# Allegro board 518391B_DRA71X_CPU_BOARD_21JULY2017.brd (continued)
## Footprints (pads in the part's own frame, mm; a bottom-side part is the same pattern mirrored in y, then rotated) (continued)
JMP402-25
  rect 0.635x0.635 smd: 1(-0.508,0)
  round 0.635 smd: 2(0.508,0) 3(1.524,0)
JUMP1X2-5635-2MM
  rect 1.422x1.422 hole 0.889: 1(0,0)
  round 1.422 hole 0.889: 2(1.981,0)
JUMP1X2-6040
  rect 1.524x1.524 hole 1.016: 1(0,0)
  round 1.524 hole 1.016: 2(0,-2.54)
JUMP1X5-6040
  rect 1.524x1.524 hole 1.016: 1(0,0)
  round 1.524 hole 1.016: 2(0,-2.54) 3(0,-5.08) 4(0,-7.62) 5(0,-10.16)
JUMP2X6-5432-2MM
  rect 1.372x1.372 hole 0.813: 1(0,0)
  round 1.372 hole 0.813: 2(1.981,0) 3(0,-1.981) 4(1.981,-1.981) 5(0,-3.962) 6(1.981,-3.962) 7(0,-5.944) 8(1.981,-5.944) 9(0,-7.925) 10(1.981,-7.925) 11(0,-9.906) 12(1.981,-9.906)
JUMP2X7-6040
  rect 1.524x1.524 hole 1.016: 1(0,0)
  round 1.524 hole 1.016: 2(2.54,0) 3(0,-2.54) 4(2.54,-2.54) 5(0,-5.08) 6(2.54,-5.08) 7(0,-7.62) 8(2.54,-7.62) 9(0,-10.16) 10(2.54,-10.16) 11(0,-12.7) 12(2.54,-12.7) 13(0,-15.24) 14(2.54,-15.24)
L402-25
  round 0.635 smd: 1(-0.508,0) 2(0.508,0)
L603-35X45
  oval 0.889x1.143 smd: 1(-0.762,0) 2(0.762,0)
L805-35X60
  oval 0.889x1.524 smd: 1(-0.965,0) 2(0.965,0)
LED603-35X45-REV
  oval 0.889x1.143 smd: 1(0.762,0) 2(-0.762,0)
LED1206-59X59
  rect 1.499x1.499 smd: 1(-1.753,0) 2(1.753,0)
MHP93-200
  round 5.08 hole 2.362: 1(0,0)
MHP125-250
  round 6.35 hole 3.175: 1(0,0)
MOLEX-34826-0124
  round 1.524 hole 0.991: 1(-7.01,1.295) 2(-5.004,1.295) 3(5.004,1.295) 4(7.01,1.295) 5(-7.01,-0.914) 6(-5.004,-0.914) 7(-2.997,-0.914) 8(-0.991,-0.914) 9(0.991,-0.914) 10(2.997,-0.914) 11(5.004,-0.914) 12(7.01,-0.914)
  round 3.556 hole 2.54: 13(-9.855,0) 14(9.855,0)
MOLEX-49225-201
  rect 0.787x1.778 smd: 1(-3.876,10.744) 2(-2.776,10.744) 3(-1.676,10.744) 4(-0.577,10.744) 5(0.523,10.744) 6(1.623,10.744) 7(2.723,10.744) 8(3.823,10.744)
  rect 1.524x2.794 smd: 9(5.893,8.153)
  rect 1.524x2.159 smd: 10(5.893,0.47)
  rect 1.753x2.21 smd: 11(5.893,-4.128) 12(-8.712,-5.144)
  rect 1.702x3.81 smd: 13(-9.398,-0.483)
  rect 1.397x3.556 smd: 14(-9.398,9.03)
  rect 1.6x1.524 smd: 15(-5.969,10.744)
NEO-M8U
  rect 0.787x1.524 smd: 1(-7,-5.88) 2(-5.9,-5.88) 3(-4.801,-5.88) 4(-3.701,-5.88) 5(-2.601,-5.88) 6(-1.501,-5.88) 7(-0.401,-5.88) 8(2.598,-5.88) 9(3.698,-5.88) 10(4.798,-5.88) 11(5.898,-5.88) 12(6.998,-5.88) 13(6.998,5.88) 14(5.898,5.88) 15(4.798,5.88) 16(3.698,5.88) 17(2.598,5.88) 18(-0.401,5.88) 19(-1.501,5.88) 20(-2.601,5.88) 21(-3.701,5.88) 22(-4.801,5.88) 23(-5.9,5.88) 24(-7,5.88)
OSC-KC2520
  rect 1.041x0.94 smd: 1(-0.914,-0.724) 2(0.914,-0.724) 3(0.914,0.724) 4(-0.914,0.724)
PM64-12X70
  oval 0.305x1.778 smd: 1(-3.749,-5.74) 2(-3.249,-5.74) 3(-2.749,-5.74) 4(-2.249,-5.74) 5(-1.75,-5.74) 6(-1.25,-5.74) 7(-0.75,-5.74) 8(-0.25,-5.74) 9(0.25,-5.74) 10(0.75,-5.74) 11(1.25,-5.74) 12(1.75,-5.74) 13(2.249,-5.74) 14(2.749,-5.74) 15(3.249,-5.74) 16(3.749,-5.74) 33(3.749,5.74) 34(3.249,5.74) 35(2.749,5.74) 36(2.249,5.74) 37(1.75,5.74) 38(1.25,5.74) 39(0.75,5.74) 40(0.25,5.74) 41(-0.25,5.74) 42(-0.75,5.74) 43(-1.25,5.74) 44(-1.75,5.74) 45(-2.249,5.74) 46(-2.749,5.74) 47(-3.249,5.74) 48(-3.749,5.74)
  oval 1.778x0.305 smd: 17(5.74,-3.749) 18(5.74,-3.249) 19(5.74,-2.749) 20(5.74,-2.249) 21(5.74,-1.75) 22(5.74,-1.25) 23(5.74,-0.75) 24(5.74,-0.25) 25(5.74,0.25) 26(5.74,0.75) 27(5.74,1.25) 28(5.74,1.75) 29(5.74,2.249) 30(5.74,2.749) 31(5.74,3.249) 32(5.74,3.749) 49(-5.74,3.749) 50(-5.74,3.249) 51(-5.74,2.749) 52(-5.74,2.249) 53(-5.74,1.75) 54(-5.74,1.25) 55(-5.74,0.75) 56(-5.74,0.25) 57(-5.74,-0.25) 58(-5.74,-0.75) 59(-5.74,-1.25) 60(-5.74,-1.75) 61(-5.74,-2.249) 62(-5.74,-2.749) 63(-5.74,-3.249) 64(-5.74,-3.749)
POWERMITE-CASE457-04
  rect 2.667x2.54 smd: 1(0,0)
  rect 0.762x1.27 smd: 2(2.349,0)
PW14-12X70
  oval 0.305x1.778 smd: 1(-1.951,-3.048) 2(-1.3,-3.048) 3(-0.65,-3.048) 4(0,-3.048) 5(0.65,-3.048) 6(1.3,-3.048) 7(1.951,-3.048) 8(1.951,3.048) 9(1.3,3.048) 10(0.65,3.048) 11(0,3.048) 12(-0.65,3.048) 13(-1.3,3.048) 14(-1.951,3.048)
PWP14-14X70-PAD
  oval 0.356x1.778 smd: 1(-1.951,-2.987) 2(-1.3,-2.987) 3(-0.65,-2.987) 4(0,-2.987) 5(0.65,-2.987) 6(1.3,-2.987) 7(1.951,-2.987) 8(1.951,2.987) 9(1.3,2.987) 10(0.65,2.987) 11(0,2.987) 12(-0.65,2.987) 13(-1.3,2.987) 14(-1.951,2.987)
  rect 3.302x2.794 smd: 15(0,0)
PWP16-14X70-PAD
  oval 0.356x1.778 smd: 1(-2.276,-2.987) 2(-1.626,-2.987) 3(-0.975,-2.987) 4(-0.325,-2.987) 5(0.325,-2.987) 6(0.975,-2.987) 7(1.626,-2.987) 8(2.276,-2.987) 9(2.276,2.987) 10(1.626,2.987) 11(0.975,2.987) 12(0.325,2.987) 13(-0.325,2.987) 14(-0.975,2.987) 15(-1.626,2.987) 16(-2.276,2.987)
  rect 4.572x3.048 smd: 17(0,0)
PWP28-14X70
  oval 0.356x1.778 smd: 1(-4.227,-2.921) 2(-3.576,-2.921) 3(-2.926,-2.921) 4(-2.276,-2.921) 5(-1.626,-2.921) 6(-0.975,-2.921) 7(-0.325,-2.921) 8(0.325,-2.921) 9(0.975,-2.921) 10(1.626,-2.921) 11(2.276,-2.921) 12(2.926,-2.921) 13(3.576,-2.921) 14(4.227,-2.921) 15(4.227,2.921) 16(3.576,2.921) 17(2.926,2.921) 18(2.276,2.921) 19(1.626,2.921) 20(0.975,2.921) 21(0.325,2.921) 22(-0.325,2.921) 23(-0.975,2.921) 24(-1.626,2.921) 25(-2.276,2.921) 26(-2.926,2.921) 27(-3.576,2.921) 28(-4.227,2.921)
  rect 7.62x2.54 smd: 29(0,0)
PWR-Q5A-SLPS319
  rect 0.711x1.397 smd: 1(-1.905,0) 2(-0.635,0) 3(0.635,0) 4(1.905,0)
  custom 1.111x1.111 smd: 5(0,2.781)
PWRJACK-CUI-PJ063BH
  round 1.092 hole 1.6 unplated: (0,-3)
  oval 3.81x1.778 hole 2.997x1.016: 1(0,-12)
  oval 3.073x1.778 hole 2.311x1.016: 2(0,-6)
  oval 1.778x3.302 hole 1.016x2.489: MTG1(-4.5,-5) MTG2(4.5,-5)
QFN32_5X5
  oval 0.254x0.838 smd: 1(-1.751,-2.515) 8(1.751,-2.515) 17(1.751,2.515) 24(-1.751,2.515)
  rect 0.254x0.838 smd: 2(-1.251,-2.515) 3(-0.751,-2.515) 4(-0.25,-2.515) 5(0.25,-2.515) 6(0.751,-2.515) 7(1.251,-2.515) 18(1.251,2.515) 19(0.751,2.515) 20(0.25,2.515) 21(-0.25,2.515) 22(-0.751,2.515) 23(-1.251,2.515)
  oval 0.838x0.254 smd: 9(2.515,-1.751) 16(2.515,1.751) 25(-2.515,1.751) 32(-2.515,-1.751)
  rect 0.838x0.254 smd: 10(2.515,-1.251) 11(2.515,-0.751) 12(2.515,-0.25) 13(2.515,0.25) 14(2.515,0.751) 15(2.515,1.251) 26(-2.515,1.251) 27(-2.515,0.751) 28(-2.515,0.25) 29(-2.515,-0.25) 30(-2.515,-0.751) 31(-2.515,-1.251)
  rect 3.404x3.404 smd: 33(0,0)
QFN84-12X12
  oval 0.889x0.279 smd: 1(-5.944,5.001) 2(-5.944,4.501) 3(-5.944,4) 4(-5.944,3.5) 5(-5.944,3) 6(-5.944,2.499) 7(-5.944,2.002) 8(-5.944,1.501) 9(-5.944,1.001) 10(-5.944,0.5) 11(-5.944,0) 12(-5.944,-0.5) 13(-5.944,-1.001) 14(-5.944,-1.501) 15(-5.944,-2.002) 16(-5.944,-2.499) 17(-5.944,-3) 18(-5.944,-3.5) 19(-5.944,-4) 20(-5.944,-4.501) 21(-5.944,-5.001) 43(5.944,-5.001) 44(5.944,-4.501) 45(5.944,-4) 46(5.944,-3.5) 47(5.944,-3.002) 48(5.944,-2.502) 49(5.944,-2.002) 50(5.944,-1.501) 51(5.944,-1.001) 52(5.944,-0.5) 53(5.944,0) 54(5.944,0.5) 55(5.944,1.001) 56(5.944,1.501) 57(5.944,2.002) 58(5.944,2.499) 59(5.944,3) 60(5.944,3.5) 61(5.944,4) 62(5.944,4.501) 63(5.944,5.001)
  oval 0.279x0.889 smd: 22(-5.001,-5.944) 23(-4.501,-5.944) 24(-4,-5.944) 25(-3.5,-5.944) 26(-3,-5.944) 27(-2.499,-5.944) 28(-2.002,-5.944) 29(-1.501,-5.944) 30(-1.001,-5.944) 31(-0.5,-5.944) 32(0,-5.944) 33(0.5,-5.944) 34(1.001,-5.944) 35(1.501,-5.944) 36(2.002,-5.944) 37(2.499,-5.944) 38(3,-5.944) 39(3.5,-5.944) 40(4,-5.944) 41(4.501,-5.944) 42(5.001,-5.944) 64(5.001,5.944) 65(4.501,5.944) 66(4,5.944) 67(3.5,5.944) 68(3.002,5.944) 69(2.502,5.944) 70(2.002,5.944) 71(1.501,5.944) 72(1.001,5.944) 73(0.5,5.944) 74(0,5.944) 75(-0.5,5.944) 76(-1.001,5.944) 77(-1.501,5.944) 78(-2.002,5.944) 79(-2.499,5.944) 80(-3,5.944) 81(-3.5,5.944) 82(-4,5.944) 83(-4.501,5.944) 84(-5.001,5.944)
  rect 5.588x5.588 smd: 85(0,0)
QSH-020-DP-A
  round 0.508 hole 1.016 unplated: (-10.06,2.667) (10.06,2.667)
  rect 0.279x2.273 smd: 1(-7.248,-2.864) 2(-7.248,2.864) 3(-6.748,-2.864) 4(-6.748,2.864) 5(-5.749,-2.864) 6(-5.749,2.864) 7(-5.249,-2.864) 8(-5.249,2.864) 9(-4.249,-2.864) 10(-4.249,2.864) 11(-3.749,-2.864) 12(-3.749,2.864) 13(-2.749,-2.864) 14(-2.749,2.864) 15(-2.249,-2.864) 16(-2.249,2.864) 17(-1.25,-2.864) 18(-1.25,2.864) 19(-0.75,-2.864) 20(-0.75,2.864) 21(0.25,-2.864) 22(0.25,2.864) 23(0.75,-2.864) 24(0.75,2.864) 25(1.75,-2.864) 26(1.75,2.864) 27(2.249,-2.864) 28(2.249,2.864) 29(3.249,-2.864) 30(3.249,2.864) 31(3.749,-2.864) 32(3.749,2.864) 33(4.749,-2.864) 34(4.749,2.864) 35(5.249,-2.864) 36(5.249,2.864) 37(6.248,-2.864) 38(6.248,2.864) 39(6.748,-2.864) 40(6.748,2.864)
  rect 2.54x0.432 smd: 41(-8.065,0) 44(8.065,0)
  rect 4.699x0.432 smd: 42(-3.175,0) 43(3.175,0)
QSH-030-01-F
  round 0.508 hole 1.016 unplated: (-10.061,2.667) (10.061,2.667)
  rect 0.279x2.273 smd: 1(-7.249,-2.865) 2(-7.249,2.865) 3(-6.749,-2.865) 4(-6.749,2.865) 5(-6.248,-2.865) 6(-6.248,2.865) 7(-5.748,-2.865) 8(-5.748,2.865) 9(-5.248,-2.865) 10(-5.248,2.865) 11(-4.75,-2.865) 12(-4.75,2.865) 13(-4.249,-2.865) 14(-4.249,2.865) 15(-3.749,-2.865) 16(-3.749,2.865) 17(-3.249,-2.865) 18(-3.249,2.865) 19(-2.748,-2.865) 20(-2.748,2.865) 21(-2.25,-2.865) 22(-2.25,2.865) 23(-1.75,-2.865) 24(-1.75,2.865) 25(-1.25,-2.865) 26(-1.25,2.865) 27(-0.749,-2.865) 28(-0.749,2.865) 29(-0.249,-2.865) 30(-0.249,2.865) 31(0.249,-2.865) 32(0.249,2.865) 33(0.749,-2.865) 34(0.749,2.865) 35(1.25,-2.865) 36(1.25,2.865) 37(1.75,-2.865) 38(1.75,2.865) 39(2.25,-2.865) 40(2.25,2.865) 41(2.748,-2.865) 42(2.748,2.865) 43(3.249,-2.865) 44(3.249,2.865) 45(3.749,-2.865) 46(3.749,2.865) 47(4.249,-2.865) 48(4.249,2.865) 49(4.75,-2.865) 50(4.75,2.865) 51(5.248,-2.865) 52(5.248,2.865) 53(5.748,-2.865) 54(5.748,2.865) 55(6.248,-2.865) 56(6.248,2.865) 57(6.749,-2.865) 58(6.749,2.865) 59(7.249,-2.865) 60(7.249,2.865)
  rect 2.54x0.432 smd: 61(-8.065,0) 64(8.065,0)
  rect 4.699x0.432 smd: 62(-3.175,0) 63(3.175,0)
R201-6P6SPC
  rect 0.47x0.381 smd: 1(-0.343,0) 2(0.343,0)
R402-25
  round 0.635 smd: 1(-0.508,0) 2(0.508,0)
R603-35X45
  oval 0.889x1.143 smd: 1(-0.762,0) 2(0.762,0)
R0612
  rect 3.175x0.889 smd: 1(0,-0.813) 2(0,0.813)
R1206-40X70
  oval 1.016x1.778 smd: 1(-1.524,0) 2(1.524,0)
RGE24-11X28-4MM
  rect 0.711x0.279 smd: 1(-1.905,1.245) 2(-1.905,0.747) 3(-1.905,0.249) 4(-1.905,-0.249) 5(-1.905,-0.747) 6(-1.905,-1.245) 13(1.905,-1.245) 14(1.905,-0.747) 15(1.905,-0.249) 16(1.905,0.249) 17(1.905,0.747) 18(1.905,1.245)
  rect 0.279x0.711 smd: 7(-1.245,-1.905) 8(-0.747,-1.905) 9(-0.249,-1.905) 10(0.249,-1.905) 11(0.747,-1.905) 12(1.245,-1.905) 19(1.245,1.905) 20(0.747,1.905) 21(0.249,1.905) 22(-0.249,1.905) 23(-0.747,1.905) 24(-1.245,1.905)
  rect 2.464x2.464 smd: 25(0,0)
RGY16-12X34
  oval 0.864x0.305 smd: 1(-2.032,-0.749) 8(2.032,-0.749) 9(2.032,0.749) 16(-2.032,0.749)
  oval 0.305x0.864 smd: 2(-1.252,-1.765) 3(-0.752,-1.765) 4(-0.251,-1.765) 5(0.249,-1.765) 6(0.749,-1.765) 7(1.25,-1.765) 10(1.25,1.765) 11(0.749,1.765) 12(0.249,1.765) 13(-0.251,1.765) 14(-0.752,1.765) 15(-1.252,1.765)
  rect 2.489x2.032 smd: 17(0,0)
RGZ48-11X34
  rect 0.279x0.864 smd: 1(-2.748,-3.531) 2(-2.25,-3.531) 3(-1.75,-3.531) 4(-1.25,-3.531) 5(-0.749,-3.531) 6(-0.249,-3.531) 7(0.249,-3.531) 8(0.749,-3.531) 9(1.25,-3.531) 10(1.75,-3.531) 11(2.25,-3.531) 12(2.748,-3.531) 25(2.748,3.531) 26(2.25,3.531) 27(1.75,3.531) 28(1.25,3.531) 29(0.749,3.531) 30(0.249,3.531) 31(-0.249,3.531) 32(-0.749,3.531) 33(-1.25,3.531) 34(-1.75,3.531) 35(-2.25,3.531) 36(-2.748,3.531)
  rect 0.864x0.279 smd: 13(3.531,-2.748) 14(3.531,-2.25) 15(3.531,-1.75) 16(3.531,-1.25) 17(3.531,-0.749) 18(3.531,-0.249) 19(3.531,0.249) 20(3.531,0.749) 21(3.531,1.25) 22(3.531,1.75) 23(3.531,2.25) 24(3.531,2.748) 37(-3.531,2.748) 38(-3.531,2.25) 39(-3.531,1.75) 40(-3.531,1.25) 41(-3.531,0.749) 42(-3.531,0.249) 43(-3.531,-0.249) 44(-3.531,-0.749) 45(-3.531,-1.25) 46(-3.531,-1.75) 47(-3.531,-2.25) 48(-3.531,-2.748)
  rect 5.334x5.334 smd: 49(0,0)
RHS48-11X34
  rect 0.279x0.864 smd: 1(-2.748,-3.531) 2(-2.25,-3.531) 3(-1.75,-3.531) 4(-1.25,-3.531) 5(-0.749,-3.531) 6(-0.249,-3.531) 7(0.249,-3.531) 8(0.749,-3.531) 9(1.25,-3.531) 10(1.75,-3.531) 11(2.25,-3.531) 12(2.748,-3.531) 25(2.748,3.531) 26(2.25,3.531) 27(1.75,3.531) 28(1.25,3.531) 29(0.749,3.531) 30(0.249,3.531) 31(-0.249,3.531) 32(-0.749,3.531) 33(-1.25,3.531) 34(-1.75,3.531) 35(-2.25,3.531) 36(-2.748,3.531)
  rect 0.864x0.279 smd: 13(3.531,-2.748) 14(3.531,-2.25) 15(3.531,-1.75) 16(3.531,-1.25) 17(3.531,-0.749) 18(3.531,-0.249) 19(3.531,0.249) 20(3.531,0.749) 21(3.531,1.25) 22(3.531,1.75) 23(3.531,2.25) 24(3.531,2.748) 37(-3.531,2.748) 38(-3.531,2.25) 39(-3.531,1.75) 40(-3.531,1.25) 41(-3.531,0.749) 42(-3.531,0.249) 43(-3.531,-0.249) 44(-3.531,-0.749) 45(-3.531,-1.25) 46(-3.531,-1.75) 47(-3.531,-2.25) 48(-3.531,-2.748)
  rect 5.334x5.334 smd: 49(0,0)
RKT24
  rect 0.203x0.965 smd: 1(-1.806,-0.965) 2(-1.405,-0.965) 3(-1.003,-0.965) 4(-0.602,-0.965) 5(-0.201,-0.965) 6(0.201,-0.965) 7(0.602,-0.965) 8(1.003,-0.965) 9(1.405,-0.965) 10(1.806,-0.965) 13(1.806,0.965) 14(1.405,0.965) 15(1.003,0.965) 16(0.602,0.965) 17(0.201,0.965) 18(-0.201,0.965) 19(-0.602,0.965) 20(-1.003,0.965) 21(-1.405,0.965) 22(-1.806,0.965)
  rect 0.965x0.203 smd: 11(1.981,-0.201) 12(1.981,0.201) 23(-1.981,0.201) 24(-1.981,-0.201)
RND36-24X10
  oval 0.254x0.61 smd: 1(-2.002,-2.896) 2(-1.501,-2.896) 3(-1.001,-2.896) 4(-0.5,-2.896) 5(0,-2.896) 6(0.498,-2.896) 7(0.998,-2.896) 8(1.499,-2.896) 9(1.999,-2.896) 19(2.002,2.896) 20(1.501,2.896) 21(1.001,2.896) 22(0.5,2.896) 23(0,2.896) 24(-0.498,2.896) 25(-0.998,2.896) 26(-1.499,2.896) 27(-1.999,2.896)
  oval 0.61x0.254 smd: 10(2.896,-2.002) 11(2.896,-1.501) 12(2.896,-1.001) 13(2.896,-0.5) 14(2.896,0) 15(2.896,0.498) 16(2.896,0.998) 17(2.896,1.499) 18(2.896,1.999) 28(-2.896,1.999) 29(-2.896,1.499) 30(-2.896,0.998) 31(-2.896,0.498) 32(-2.896,0) 33(-2.896,-0.5) 34(-2.896,-1.001) 35(-2.896,-1.501) 36(-2.896,-2.002)
  rect 3.81x3.81 smd: 37(0,0)
RVC20
  rect 0.279x0.711 smd: 1(-1.245,-1.422) 2(-0.747,-1.422) 3(-0.249,-1.422) 4(0.249,-1.422) 5(0.747,-1.422) 6(1.245,-1.422) 11(1.245,1.422) 12(0.747,1.422) 13(0.249,1.422) 14(-0.249,1.422) 15(-0.747,1.422) 16(-1.245,1.422)
  rect 0.711x0.279 smd: 7(1.905,-0.747) 8(1.905,-0.249) 9(1.905,0.249) 10(1.905,0.747) 17(-1.905,0.747) 18(-1.905,0.249) 19(-1.905,-0.249) 20(-1.905,-0.747)
  rect 2.388x1.6 smd: 21(0,0)
SAMTEC-MUSB
  round 0.508 hole 0.889 unplated: (-2.197,-2.591) (2.197,-2.591)
  rect 0.508x2.286 smd: 1(-1.6,0) 2(-0.8,0) 3(0,0) 4(0.8,0) 5(1.6,0)
  rect 2.007x2.489 smd: 6(-4.445,-0.102) 7(4.445,-0.102) 8(-4.445,-5.613) 9(4.445,-5.613)
SM-7351-CAP-0402
  round 0.635 smd: 1(-0.508,0) 2(0.508,0)
SM-7351-CAP-0508
  rect 0.457x1.778 smd: 1(-0.445,0) 2(0.445,0)
SM-7351-RES-0402
  round 0.635 smd: 1(-0.508,0) 2(0.508,0)
SMA2-78SQ
  rect 1.981x1.981 smd: 1(-2.007,0) 2(2.007,0)
SMC-80X128
  rect 2.032x3.251 smd: 1(-3.124,0) 2(3.124,0)
SO8-25X75
  oval 0.635x1.905 smd: 1(-1.905,-2.794) 2(-0.635,-2.794) 3(0.635,-2.794) 4(1.905,-2.794) 5(1.905,2.794) 6(0.635,2.794) 7(-0.635,2.794) 8(-1.905,2.794)
SO8-25X75-295
  oval 0.635x2.54 smd: 1(-1.905,-3.086) 2(-0.635,-3.086) 3(0.635,-3.086) 4(1.905,-3.086) 5(1.905,3.086) 6(0.635,3.086) 7(-0.635,3.086) 8(-1.905,3.086)
SOD323
  rect 1.092x0.508 smd: 1(-1.194,0) 2(1.194,0)
SOD523
  rect 0.762x0.381 smd: 1(0.838,0) 2(-0.838,0)
SOT23-28X44
  rect 0.711x1.118 smd: 1(-0.965,-1.067) 2(0.965,-1.067) 3(0,1.067)
SOT363-16X45
  rect 0.406x0.635 smd: 1(-0.65,-0.978) 2(0,-0.978) 3(0.65,-0.978) 4(0.65,0.978) 5(0,0.978) 6(-0.65,0.978)
SSOP-16
  oval 0.356x1.778 smd: 1(-2.223,-2.692) 2(-1.587,-2.692) 3(-0.953,-2.692) 4(-0.318,-2.692) 5(0.318,-2.692) 6(0.953,-2.692) 7(1.587,-2.692) 8(2.223,-2.692) 9(2.223,2.692) 10(1.587,2.692) 11(0.953,2.692) 12(0.318,2.692) 13(-0.318,2.692) 14(-0.953,2.692) 15(-1.587,2.692) 16(-2.223,2.692)
ST_3500SM
  round 1.016 hole 1.6 unplated: (0,3.797) (0,-3.188)
  rect 2.54x2.388 smd: 1(-3.683,4.915) 2(-3.48,-4.407) 3(3.683,3.01)
  rect 2.921x2.489 smd: 4(0.762,-8.42)
SW2-30X50-TDA
  rect 0.762x1.27 smd: 1(-0.635,-3.81) 2(0.635,-3.81) 3(0.635,3.81) 4(-0.635,3.81)
SW6-30X50-TDA
  rect 0.762x1.27 smd: 1(-3.175,-3.81) 2(-1.905,-3.81) 3(-0.635,-3.81) 4(0.635,-3.81) 5(1.905,-3.81) 6(3.175,-3.81) 7(3.175,3.81) 8(1.905,3.81) 9(0.635,3.81) 10(-0.635,3.81) 11(-1.905,3.81) 12(-3.175,3.81)
TP1-70X135
  rect 2.286x3.937 smd: 1(0,0)
TP20
  round 0.508 smd: 1(0,0)
TP-20RD10
  round 0.508 hole 0.254: 1(0,0)
TP-30RD13
  round 0.762 hole 0.33: 1(0,0)
TSDSON8
  custom 0.248x0.248 smd: 1(-0.33,-1.499)
  rect 0.356x1.016 smd: 4(0.978,-1.486)
  custom 0.572x0.572 smd: 5(0,0.673)
TSSOP16-14X70
  oval 0.356x1.778 smd: 1(-2.276,-2.987) 2(-1.626,-2.987) 3(-0.975,-2.987) 4(-0.325,-2.987) 5(0.325,-2.987) 6(0.975,-2.987) 7(1.626,-2.987) 8(2.276,-2.987) 9(2.276,2.987) 10(1.626,2.987) 11(0.975,2.987) 12(0.325,2.987) 13(-0.325,2.987) 14(-0.975,2.987) 15(-1.626,2.987) 16(-2.276,2.987)
unnamed#2
  round 1.27 smd: 1(0,0)
WIFIBTMOD68
  rect 0.61x1.27 smd: 1(-9.5,-8.315) 2(-8.5,-8.315) 3(-7.5,-8.315) 4(-6.5,-8.315) 5(-5.5,-8.315) 6(-4.5,-8.315) 7(-3.5,-8.315) 8(-2.5,-8.315) 9(-1.5,-8.315) 10(-0.5,-8.315) 11(0.5,-8.315) 12(1.5,-8.315) 13(2.5,-8.315) 14(3.5,-8.315) 15(4.5,-8.315) 16(5.5,-8.315) 17(6.5,-8.315) 18(7.5,-8.315) 19(8.5,-8.315) 20(9.5,-8.315) 35(9.5,8.315) 36(8.5,8.315) 37(7.5,8.315) 38(6.5,8.315) 39(5.5,8.315) 40(4.5,8.315) 41(3.5,8.315) 42(2.5,8.315) 43(1.5,8.315) 44(0.5,8.315) 45(-0.5,8.315) 46(-1.5,8.315) 47(-2.5,8.315) 48(-3.5,8.315) 49(-4.5,8.315) 50(-5.5,8.315) 51(-6.5,8.315) 52(-7.5,8.315) 53(-8.5,8.315) 54(-9.5,8.315)
  rect 1.27x0.61 smd: 21(10.065,-6.5) 22(10.065,-5.5) 23(10.065,-4.5) 24(10.065,-3.5) 25(10.065,-2.5) 26(10.065,-1.5) 27(10.065,-0.5) 28(10.065,0.5) 29(10.065,1.5) 30(10.065,2.5) 31(10.065,3.5) 32(10.065,4.5) 33(10.065,5.5) 34(10.065,6.5) 55(-10.065,6.5) 56(-10.065,5.5) 57(-10.065,4.5) 58(-10.065,3.5) 59(-10.065,2.5) 60(-10.065,1.5) 61(-10.065,0.5) 62(-10.065,-0.5) 63(-10.065,-1.5) 64(-10.065,-2.5) 65(-10.065,-3.5) 66(-10.065,-4.5) 67(-10.065,-5.5) 68(-10.065,-6.5)
XTAL4-55X47-3225
  rect 1.397x1.194 smd: 1(-1.092,-0.838) 2(1.092,-0.838) 3(1.092,0.838) 4(-1.092,0.838)
XTAL4-ABM11
  rect 0.889x0.813 smd: 1(-0.711,-0.559) 2(0.711,-0.559) 3(0.711,0.559) 4(-0.711,0.559)
XTAL150SMD_125X196
  rect 1.778x2.159 smd: 1(-1.9,0) 2(1.9,0)

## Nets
1V8_I2C1_SCL: P9.2 R245.2 U21.52(GNSS_I2C_SCL) U26.3(SCL1)
1V8_I2C1_SDA: P9.4 R246.2 U21.50(GNSS_I2C_SDA) U26.4(SDA1)
1V8_RSTOUTN: P9.14 R296.1 U31.M5(RSTN) U54.4(O)
GND: ANT1.2(GND) C1.2 C2.2 C3.2 C4.1 C5.2 C6.1 C7.2 C8.2 C9.2 C10.1 C11.2 C12.2 C15.2 C16.1 C17.2 C18.2 C19.2 C20.2 C21.2 C22.2 C23.2 C24.2 C25.2 C27.2 C28.1 C29.2 C31.2 C32.2 C33.2 C34.2 C35.2 C37.2 C38.2 C40.2 C41.1 C42.2 C43.1 C44.2 C45.2 C48.1 C49.2 C51.1 C53.2 C54.1 C56.2 C57.2 C58.2 C59.2 C60.2 C62.2 C63.1 C64.2 C65.2 C66.1 C67.2 C68.2 C69.2 C70.1 C71.2 C72.2 C73.2 C74.2 C75.2 C77.2 C78.2 C81.2 C82.2 C83.2 C84.2 C85.1 C86.2 C89.2 C90.1 C91.2 C92.2 C95.2 C96.2 C98.2 C100.2 C101.2 C102.1 C104.2 C106.1 C108.2 C110.2 C111.2 C114.2 C116.2 C117.1 C118.2 C119.2 C120.2 C122.2 C123.2 C126.2 C127.2 C128.2 C129.2 C130.2 C131.2 C132.2 C133.2 C134.1 C135.1 C142.2 C143.1 C144.1 C145.2 C146.2 C153.1 C154.1 C155.1 C156.1 C157.1 C158.1 C160.1 C161.1 C163.1 C164.1 C165.2 C166.2 C167.2 C168.1 C171.2 C172.1 C173.2 C174.2 C175.2 C176.2 C177.2 C178.1 C181.2 C182.2 C186.1 C187.2 C188.2 C189.2 C190.2 C191.2 C194.2 C195.2 C199.2 C201.2 C203.2 C204.2 C205.2 C207.2 C208.2 C210.2 C212.2 C213.2 C214.2 C218.2 C219.2 C222.2 C224.2 C225.2 C226.2 C227.2 C228.2 C231.2 C234.2 C235.2 C237.2 C238.2 C239.2 C241.2 C242.2 C243.2 C244.2 C245.2 C246.2 C247.2 C248.2 C249.2 C250.2 C252.2 C253.2 C254.2 C256.2 C258.2 C259.2 C260.2 C261.2 C263.2 C264.2 C265.2 C267.2 C268.2 C269.2 C271.2 C272.2 C273.2 C274.2 C275.1 C277.2 C278.2 C279.2 C280.2 C281.2 C282.2 C283.2 C284.2 C285.2 C286.2 C287.2 C288.2 C289.2 C290.2 C291.2 C293.2 C294.2 C295.2 C296.2 C297.2 C298.2 C299.2 C300.2 C301.2 C302.2 C303.2 C304.2 C305.2 C306.2 C307.2 C308.2 C309.2 C310.2 C311.2 C312.2 C313.2 C314.2 C315.2 C316.2 C317.1 C318.2 C319.2 C320.2 C321.2 C322.2 C323.2 C324.2 C325.2 C326.2 C327.2 C328.2 C329.2 C331.2 C332.2 C333.2 C334.2 C335.2 C336.2 C337.2 C338.2 C339.2 C340.2 C341.2 C342.2 C343.2 C344.2 C345.2 C346.1 C347.2 C348.2 C349.2 C350.2 C351.2 C352.2 C353.2 C354.2 C356.2 C357.2 C358.2 C359.2 C360.1 C361.2 C362.2 C363.2 C364.2 C365.1 C366.2 C367.2 C368.2 C369.2 C370.2 C372.2 C373.2 C374.2 C375.1 C377.2 C378.2 C379.2 C380.2 C381.2 C382.2 C383.2 C384.1 C385.2 C387.2 C388.2 C389.2 C390.2 C391.2 C392.2 C393.2 C394.2 C395.2 C396.2 C397.1 C398.1 C401.2 C402.2 C403.2 C404.1 C405.2 C406.2 C407.2 C408.2 C409.2 C410.2 C411.2 C412.2 C426.2 C427.2 C428.2 C429.2 C430.2 C431.2 C432.2 C433.2 C434.2 C435.2 C436.2 C437.2 C439.2 C440.2 C441.2 C442.1 C443.2 C444.2 C445.2 C446.1 C447.2 C448.1 C450.2 C454.2 C455.1 C456.1 C457.1 C458.2 C462.2 C463.2 C464.2 C465.2 C466.2 C467.2 C468.1 C469.2 C470.2 C471.2 C472.2 C474.2 C475.2 C476.2 C477.2 C478.1 C479.2 C480.2 C481.2 C482.1 C483.2 C484.2 C485.1 C486.2 C487.2 C488.2 C489.1 C493.2 C495.2 C496.2 C497.2 C498.1 C499.2 C500.1 C503.2 C504.2 C505.1 C506.2 C507.2 C508.2 C509.2 C510.2 C511.2 C512.1 C514.2 C515.2 C516.2 C517.2 C518.2 C519.2 C521.2 C522.2 C523.2 C524.2 C525.2 C526.2 C527.2 C528.2 C529.1 C532.2 C533.2 C534.1 C536.2 C537.2 C538.2 C539.1 C540.2 C541.2 C542.2 C543.2 C544.2 C545.2 C546.2 C547.2 C548.2 C549.1 C550.2 C551.2 C552.2 C553.2 C554.1 D1.2(ANODE) D2.2(ANODE) D7.2(ANODE) D12.2 D13.2 D14.2 D15.3 D17.2 D18.3 D21.1(CATHODE) D23.2(ANODE) D24.2(ANODE) DPX1.1(GND#1) DPX1.3(GND#3) DPX1.5(GND#5) DS1.1(CATHODE) E1.2 E2.2 E3.2 E4.2 E5.2 E6.2 E7.2 J1.4(GND4) J1.7(GND8) J1.G1 J1.G2 J2.4(GND4) J2.7(GND8) J2.G1 J2.G2 J3.2 J4.3 J4.4 J6.2 J6.3 J6.4 J6.5 J7.5(USBVSS) J10.2 J11.2 J12.2 J13.2 J14.16(GND16) J14.57(GND57) J14.58(GND58) J14.61(GNDCT1) J14.62(GNDCT2) J14.63(GNDCT3) J14.64(GNDCT4) J15.2 J15.12 J15.14 J16.2 J16.3 J16.4 J16.5 J17.5 J17.6 J18.2 J18.3 J18.4 J18.5 J19.3 J19.4 J19.6 J19.11 J19.17 J19.23 J19.28 J19.36 J19.40 J19.46 J19.52 J19.58 J19.63 J19.69 J19.75 J19.81 J19.86 J19.93 J19.98 J19.104 J19.109 J19.115 J19.118 J20.3 J21.7 J21.16 J21.25 J21.34 J21.40 J21.41 J21.42 J22.2 J22.MTG1 J22.MTG2 L7.1 L8.1 L10.1 L11.1 L25.1 L26.1 L29.1 L30.1 L43.1 L50.1 M1.1 M2.1 M3.1 M4.1 M5.1 M6.1 M9.1 M10.1 M11.1 M12.1 M13.1 P1.2(D2 SHIELD) P1.5(D1 SHIELD) P1.8(D0 SHIELD) P1.11(CK SHIELD) P1.17(GND) P1.MTG1 P1.MTG2 P1.MTG3 P1.MTG4 P2.4 P2.SH1 P2.SH2 P2.SH3 P2.SH4 P3.1(SHIELD) P4.1(SHIELD) P5.2 P5.3 P5.4 P5.5 P6.1(SHIELD) P7.1(SHIELD) P8.1(SHIELD) P9.12 P9.16 P9.24 P9.41(SH_GND.1) P9.42(SH_GND.2) P9.43(SH_GND.4) P9.44(SH_GND.3) P10.6(VSS) Q1.1(S2) Q1.4(S2) Q2.1(S2) Q2.4(S2) Q8.1(S1) Q10.1(S) Q11.1(S2) Q11.4(S2) Q12.1(S2) Q12.4(S2) R4.2 R5.2 R6.2 R11.2 R13.2 R17.2 R19.2 R26.1 R32.2 R36.1 R37.2 R39.1 R49.1 R50.2 R52.2 R53.2 R54.2 R56.1 R64.2 R76.2 R78.2 R104.1 R106.1 R110.1 R112.2 R114.2 R115.2 R118.1 R126.2 R141.1 R142.1 R144.2 R146.1 R147.1 R155.2 R157.1 R160.1 R161.1 R176.2 R177.2 R195.2 R197.2 R199.1 R205.2 R207.2 R222.1 R223.1 R224.1 R225.2 R235.2 R238.1 R240.1 R244.1 R248.1 R251.2 R255.2 R259.2 R261.2 R275.2 R294.1 R298.2 R301.1 R302.2 R303.2 R309.1 R315.1 R318.1 R320.2 R321.2 R322.2 R330.2 R332.2 R333.1 R337.2 R340.2 R343.1 R353.1 R355.2 R359.1 R361.2 R362.2 R367.2 R368.2 R369.2 R373.1 R375.2 R379.2 R380.2 R381.2 R382.2 R383.2 R384.2 R386.1 R387.1 R390.2 R396.1 R397.1 R398.2 R401.2 R409.2 R423.2 R425.2 R432.2 RJ1.3 RJ6.1 RJ7.1 RJ10.1 RJ14.1 RJ16.3 RJ17.3 RJ18.1 RJ19.1 RJ20.1 RJ21.1 RJ22.1 RJ23.1 RJ24.1 RJ25.1 RU1.8(GND) RU1.15(O\E\) RU2.8(GND) RU2.15(O\E\) TP13.1 TP16.1 TP17.1 TP39.1 TP60.1 TP63.1 TP64.1 TP65.1 TP66.1 U1.1(GND#1) U1.9(GND#9) U2.3(GND#3) U2.8(GND#8) U3.2(GND) U4.2(GND) U5.2(GND) U6.2(GND) U7.2(GND) U8.2(GND) U9.2(GND) U10.2(GND) U11.11(GND) U11.21(PAD) U12.4(GND#4) U12.13(GND#13) U13.3(GND) U14.3(GND) U15.10(AGND) U15.15(PGND#15) U15.16(PGND#16) U15.17(TPAD) U17.5(GND1) U17.13(GND2) U17.18(GND3) U18.3(AGND) U18.9(PGND) U18.25(DAP) U19.10(AGND) U19.13(ISNS(-)) U19.14(ISNS(+)) U19.22(PGND) U19.29(PAD) U20.5(GND) U20.9(TPAD) U21.1(GND#1) U21.2(GND#2) U21.14(GND#14) U21.18(GND#18) U21.20(GND#20) U21.26(GND#26) U21.28(GND#28) U21.33(GND#33) U21.35(GND#35) U21.45(GND#45) U21.47(GND#47) U21.53(GND#53) U21.54(GND#54) U21.56(GND#56) U21.57(GND#57) U21.59(GND#59) U21.64(GND#64) U21.66(GND#66) U21.67(GND#67) U22.1(A0) U22.2(A1) U22.3(NC) U22.4(VSS) U23.A9(VSS.1) U23.B1(VSSQ.1) U23.B3(VSS.2) U23.B9(VSSQ.2) U23.D1(VSSQ.3) U23.D8(VSSQ.4) U23.E1(VSS.3) U23.E2(VSSQ.5) U23.E8(VSSQ.6) U23.F9(VSSQ.7) U23.G1(VSSQ.8) U23.G8(VSS.4) U23.G9(VSSQ.9) U23.J2(VSSDL) U23.J8(VSS.5) U23.M1(VSS.6) U23.M9(VSS.7) U23.P1(VSS.8) U23.P9(VSS.9) U23.T1(VSS.10) U23.T9(VSS.11) U24.8(GND#8) U24.9(GND#9) U24.14(2OE) U24.15(1OE) U24.17(PAD) U25.7(VDD_USB) U25.10(GND#10) U25.12(GND#12) U25.13(GND#13) U25.24(GND#24) U26.1(GND) U27.A1(VSS_1) U27.A25(VSS_2) U27.AA7(VSS_78) U27.AA8(VSS_79) U27.AA9(VSS_80) U27.AA13(VSS_27) U27.AA15(VSS_86) U27.AB8(VSS_81) U27.AB11(VSSA_OSC1) U27.AC11(XI_OSC1) U27.AC13(VSS_82) U27.AE1(VSS_83) U27.AE15(VSS_84) U27.AE25(VSS_85) U27.G8(VSS_3) U27.G13(VSS_4) U27.G16(VSS_5) U27.H8(VSS_6) U27.H10(VSS_7) U27.H12(VSS_8) U27.H14(VSS_9) U27.H16(VSS_10) U27.H18(VSS_11) U27.H19(VSS_12) U27.J10(VSS_13) U27.J12(VSS_14) U27.J14(VSS_15) U27.J17(VSS_16) U27.K9(VSS_17) U27.K11(VSS_18) U27.K13(VSS_19) U27.K15(VSS_20) U27.K17(VSS_21) U27.L8(VSS_22) U27.L11(VSS_23) U27.L13(VSS_24) U27.L15(VSS_25) U27.L18(VSS_26) U27.M8(VSS_28) U27.M9(VSS_29) U27.M12(VSS_30) U27.M14(VSS_31) U27.M16(VSS_32) U27.M18(VSS_33) U27.M20(VSS_34) U27.N12(VSS_35) U27.N14(VSS_36) U27.N16(VSS_37) U27.N17(VSS_38) U27.N20(VSS_39) U27.P9(VSS_40) U27.P11(VSS_41) U27.P13(VSS_42) U27.P15(VSS_43) U27.P17(VSS_44) U27.P19(VSS_45) U27.R8(VSS_46) U27.R9(VSS_47) U27.R11(VSS_48) U27.R13(VSS_49) U27.R15(VSS_50) U27.R18(VSS_51) U27.R19(VSS_52) U27.T8(VSS_53) U27.T10(VSS_54) U27.T12(VSS_55) U27.T14(VSS_56) U27.T16(VSS_57) U27.T18(VSS_58) U27.U10(VSS_59) U27.U12(VSS_60) U27.U14(VSS_61) U27.U16(VSS_62) U27.U17(VSS_63) U27.U19(VSS_64) U27.V8(VSS_65) U27.V9(VSS_66) U27.V11(VSS_67) U27.V13(VSS_68) U27.V15(VSS_69) U27.V17(VSS_70) U27.V19(VSS_71) U27.W9(VSS_72) U27.W19(VSS_73) U27.Y7(VSS_74) U27.Y14(VSS_75) U27.Y16(VSS_76) U27.Y17(VSS_77) U28.1(GND1) U28.17(GND4) U28.28(GND6) U28.33(GND7) U28.36(GND8) U28.39(GND9) U28.46(GND10) U28.49(GND11) U28.52(GND12) U29.A9(VSS.1) U29.B1(VSSQ.1) U29.B3(VSS.2) U29.B9(VSSQ.2) U29.D1(VSSQ.3) U29.D8(VSSQ.4) U29.E1(VSS.3) U29.E2(VSSQ.5) U29.E8(VSSQ.6) U29.F9(VSSQ.7) U29.G1(VSSQ.8) U29.G8(VSS.4) U29.G9(VSSQ.9) U29.J2(VSSDL) U29.J8(VSS.5) U29.M1(VSS.6) U29.M9(VSS.7) U29.P1(VSS.8) U29.P9(VSS.9) U29.T1(VSS.10) U29.T9(VSS.11) U30.15(FSEL) U30.18(RES1) U30.49(DAP(PWRPAD)) U31.G2(VSS.1) U31.G3(VSS.2) U31.G4(VSS.3) U31.G5(VSS.4) U31.G6(VSS.5) U31.G7(VSS.6) U31.G8(VSS.7) U31.G9(VSS.8) U31.H2(VSSQ.1) U31.H9(VSSQ.2) U31.J5(VSS.9) U31.L3(VSSQ.3) U31.L8(VSSQ.4) U31.M4(VSSQ.5) U31.M7(VSSQ.6) U31.P2(VSSQ.7) U31.P9(VSSQ.8) U32.20(VPROG) U32.41(REFGND) U32.49(PAD) U33.6(BISTEN) U33.44(TESTEN) U33.49(DAP(PWRPAD)) U34.14(SMODE) U34.15(NVMISO) U34.16(NVMOSI) U34.17(NVSSB) U34.18(NVSCLK) U34.36(DOUT0) U34.37(GPO1) U34.38(GPO0) U34.39(DIN0) U34.46(CLKO) U34.49(GND) U35.4(PGND) U35.8(GND) U35.11(PWRPAD) U36.34(SMMODE) U36.56(DFS1) U36.57(DCLK1) U36.62(DIFS4) U36.63(DICLK4) U36.65(DIFS3) U36.66(DICLK3) U36.68(DIFS2) U36.69(DICLK2) U36.70(DIN2) U36.71(DIFS1) U36.72(DICLK1) U36.73(DIN1) U36.74(GP1) U36.75(GP2) U36.76(GP0) U36.77(DIN0) U36.78(DICLK0) U36.79(DIFSO) U36.81(ICP) U36.85(EPAD) U37.12(EVSS_1) U37.21(AW0VSS) U37.33(A0VSS) U37.50(ISOVSS) U37.61(EVSS_2) U38.2(A1) U38.3(NC) U38.4(VSS) U39.5(GND) U39.9(TPAD) U40.37(GND) U41.4(GND) U41.9(PAD) U42.1(GND) U42.9(PAD) U43.2(GND) U43.15(TAB(GND)) U44.12(GND) U44.17(PAD) U45.2(GND) U46.2(GND) U47.5(GND) U48.5(GND) U48.9(TPAD) U49.4(GND) U49.9(PAD) U50.6(AGND) U50.8(PGND) U50.9(PAD) U51.2(GND) U51.15(TAB(GND)) U52.4(GND.1) U52.17(GND.2) U52.20(GND.3) U52.24(AGND) U52.26(TEST) U52.33(PWRPAD) U53.2(GND) U54.2(I) U54.3(GND) U55.1(1OE) U55.4(2OE) U55.7(GND) U55.10(3OE) U55.13(4OE) U56.1(1OE) U56.4(2OE) U56.7(GND) U56.10(3OE) U56.13(4OE) U57.2(GND) U58.2(GND) U59.2(GND) U60.2(GND) U61.2(GND) U62.2(GND) U63.2(GND) U64.2(GND) U65.2(GND) U66.4(GND) U67.4(GND) U68.4(GND) U69.4(GND) U70.5(GND) U70.9(PWR_PAD) U71.3(GND) U72.3(GND) U73.2(GND) U74.1(A1) U74.2(A0) U74.7(GND) U75.1(OE) U75.3(GND) U76.2(GND) X2.2(GND1) X2.4(GND2) Y1.2(GND) Y2.2(GND1) Y2.4(GND2)
GND_EARTH: J7.6(SHIELD1) J7.7(SHIELD2) J7.8(SHIELD3) J7.9(SHIELD4)
VBAT: J4.1 J4.2 J22.1 R12.1 U74.8(VBUS) U74.10(VIN+)
VBAT_A: C65.1 C117.2 C316.1 C317.2 C360.2 C363.1 C384.2 C387.1 C396.1 C397.2 L4.2 TP5.1(TP) U28.2(PVDD1) U28.3(VBAT) U28.29(PVDD2) U28.30(PVDD3) U28.42(PVDD4) U28.43(PVDD5) U28.55(PVDD6) U28.56(PVDD7)
VBAT_F: C31.1 C32.1 C58.1 D9.2(ANODE) L5.2 Q6.5(D) R45.1 TP15.1(TP)
VBAT_PM: C24.1 D3.ANODE1 D3.ANODE2 D22.1(CATHODE) Q3.1(S1) Q3.2(S2) Q3.3(S3) R12.2 U16.4(ANODE) U74.9(VIN-)
VBAT_SYS: C1.1 C2.1 C3.1 C23.1 C29.1 C37.1 C38.1 C552.1 D19.2(A) L1.2 Q9.5(D) R218.2 R430.2 R431.2 TP1.1(TP) U18.15(VIN)
VBUS1_5V0: C4.2 C5.1 C9.1 J1.1(VBUS) R1.1 R196.1 U11.15(OUT#15) U11.16(OUT#16)
VBUS2_5V0: C6.2 J2.1(VBUS) R194.1 U12.2(VBUS_CON) U12.3(VBUS_SON)
VCC_APL: C258.1 J3.5 R189.2 U1.8(VCC)
VCC_LM5141: C45.1 D5.2(ANODE) U18.10(VCC)
VCC_LM5175: C42.1 D6.2(A) D8.2(A) R48.2 U19.23(VCC)
VDD33_DSU921: C122.1 C429.1 L17.1 U30.22(VDD33)
VDD_1P1_CSI: C479.1 C485.2 U33.20(VDD_1P1_CSI)
VDD_1P1_D: C134.2 C142.1 U33.3(VDD_1P1_D)
VDD_1P1_FPD: C171.1 C172.2 U33.34(VDD_1P1_FPD)
VDD_1P8: C135.2 C471.1 C486.1 L19.1 U33.36(VDD_1P8_1) U33.45(VDD_1P8_0)
VDD_1P8_CSI: C468.2 C472.1 L59.1 U33.17(VDD_1P8)
VDD_1P8_FPD: C167.1 C480.1 C487.1 L24.1 U33.31(VDD_1P8_FPD1) U33.40(VDD_1P8_FPD0)
VDD_1V8_SW: L21.2 U32.19(SPMS4_SW)
VDD_CORE_AVS: C166.1 C303.1 C321.1 C323.1 C332.1 C341.1 C344.1 C347.1 C348.1 C373.1 C551.1 L23.1 U27.J15(VDD_1) U27.J16(VDD_2) U27.J18(VDD_3) U27.K12(VDD_4) U27.K18(VDD_5) U27.L12(VDD_6) U27.L17(VDD_7) U27.M11(VDD_8) U27.M13(VDD_9) U27.M15(VDD_10) U27.M17(VDD_11) U27.N11(VDD_12) U27.N13(VDD_13) U27.N15(VDD_14) U27.N18(VDD_15) U27.P10(VDD_16) U27.P12(VDD_17) U27.P14(VDD_18) U27.P16(VDD_19) U27.P18(VDD_20) U27.R10(VDD_21) U27.R12(VDD_22) U27.R14(VDD_23) U27.R16(VDD_24) U27.R17(VDD_25) U27.T9(VDD_26) U27.T11(VDD_27) U27.T13(VDD_28) U27.T15(VDD_29) U27.T17(VDD_30) U27.U9(VDD_31) U27.U11(VDD_32) U27.U13(VDD_33) U27.U15(VDD_34) U27.U18(VDD_35) U27.V10(VDD_36) U27.V12(VDD_37) U27.V14(VDD_38) U27.V16(VDD_39) U27.V18(VDD_40) U27.W10(VDD_41) U27.W12(VDD_42) U27.W14(VDD_43) U27.W16(VDD_44) U32.33(SMPS1_FDBK)
VDD_CORE_SW: L23.2 U32.31(SPMS1_SW)
VDD_DDR_1V35: C80.2 C84.1 C89.1 C96.1 C98.1 C143.2 C153.2 C155.2 C157.2 C165.1 C272.1 C273.1 C274.1 C278.1 C279.1 C280.1 C289.1 C293.1 C294.1 C295.1 C297.1 C299.1 C300.1 C304.1 C305.1 C307.1 C311.1 C312.1 C313.1 C314.1 C315.1 C319.1 C325.1 C326.1 C327.1 C328.1 C336.1 C337.1 C338.1 C351.1 C352.1 C354.1 C377.1 C378.1 C382.1 C383.1 C386.2 C391.1 C392.1 C413.2 C414.2 C415.2 C416.2 C417.2 C418.2 C419.2 C420.2 C421.2 C422.2 C423.2 C424.2 C425.2 L22.1 R117.2 U23.A1(VDDQ.1) U23.A8(VDDQ.2) U23.B2(VDD.1) U23.C1(VDDQ.3) U23.C9(VDDQ.4) U23.D2(VDDQ.5) U23.D9(VDD.2) U23.E9(VDDQ.6) U23.F1(VDDQ.7) U23.G7(VDD.3) U23.H2(VDDQ.8) U23.H9(VDDQ.9) U23.K2(VDDL) U23.K8(VDD.4) U23.N1(VDD.5) U23.N9(VDD.6) U23.R1(VDD.7) U23.R9(VDD.8) U27.T19(VDDS_DDR1_1) U27.T20(VDDS_DDR1_2) U27.V20(VDDS_DDR1_3) U27.W17(VDDS_DDR1_4) U27.W18(VDDS_DDR1_5) U27.W20(VDDS_DDR1_6) U29.A1(VDDQ.1) U29.A8(VDDQ.2) U29.B2(VDD.1) U29.C1(VDDQ.3) U29.C9(VDDQ.4) U29.D2(VDDQ.5) U29.D9(VDD.2) U29.E9(VDDQ.6) U29.F1(VDDQ.7) U29.G7(VDD.3) U29.H2(VDDQ.8) U29.H9(VDDQ.9) U29.K2(VDDL) U29.K8(VDD.4) U29.N1(VDD.5) U29.N9(VDD.6) U29.R1(VDD.7) U29.R9(VDD.8) U32.28(SMPS2_FDBK) U35.2(VLDOIN)
VDD_DDR_SW: L22.2 U32.30(SPMS2_SW)
VDD_DSP_AVS: C126.1 C357.1 C361.1 C362.1 C367.1 C368.1 C370.1 C385.1 C393.1 C401.1 C402.1 C403.1 C536.1 C537.1 L18.1 U27.H9(VDD_DSP_1) U27.H11(VDD_DSP_2) U27.H13(VDD_DSP_3) U27.J9(VDD_DSP_4) U27.J11(VDD_DSP_5) U27.J13(VDD_DSP_6) U32.9(SMPS3_FDBK)
VDD_DSP_SW: L18.2 U32.11(SMPS3_SW)
VDDA_LM5141: C53.1 R34.2 R35.2 R221.2 U18.2(VDDA)
VDDI_MMC2: C433.1 C436.1 U31.E4(VDDIM)
VDDIO_DSU921: C116.1 C409.1 L16.2 U30.30(VDDIO)
VDDR_VREFSTL: C80.1 C82.1 C91.1 C164.2 C386.1 U23.H1(VREFDQ) U23.M8(VREFCA) U27.Y20(VREF_DDR1) U29.H1(VREFDQ) U29.M8(VREFCA) U35.6(REFOUT)
VDDS_1V8: C77.1 C108.1 C130.1 C271.1 C291.1 C298.1 C318.1 C335.1 C342.1 C369.1 C379.1 C380.1 C390.1 C411.1 C427.1 C428.1 C430.1 C431.1 C432.1 C434.1 C550.1 L19.2 L21.1 L24.2 L59.2 P9.38 P9.40 Q8.2(G1) R59.1 R127.2 R170.1 R171.1 R245.1 R246.1 R268.1 R269.1 R270.1 R271.1 R272.1 R273.1 R289.1 R291.1 R295.1 R296.2 R300.1 R338.1 R339.1 RJ12.1 U21.34(VIO) U24.1(VCCA) U26.2(VREF1) U27.AA19(VDDS18V_DDR1_3) U27.F7(VDDSHV11_1) U27.G7(VDDSHV11_2) U27.G11(VDDS18V_1) U27.H7(VDDSHV11_3) U27.H20(VDDS18V_2) U27.P7(VDDS_MLB_1) U27.P20(VDDS18V_DDR1_1) U27.R7(VDDS_MLB_2) U27.U7(VDDSHV7_1) U27.U8(VDDSHV7_2) U27.W7(VDDS18V_3) U27.Y18(VDDS18V_4) U27.Y19(VDDS18V_DDR1_2) U31.H3(VCCQ.1) U31.H8(VCCQ.2) U31.L2(VCCQ.3) U31.L4(VCCQ.4) U31.L7(VCCQ.5) U31.L9(VCCQ.6) U31.P3(VCCQ.7) U31.P8(VCCQ.8) U32.17(SMPS4_FDBK) U75.5(VCC) Y1.4(VCC)
3INP_A: C103.1 R261.1 U28.11(GND3)
4INM_A: C110.1 U28.10(GVDD2)
4INP_A: C109.1 C381.1 U28.9(GVDD1)
APL_RSTN: R190.1 U27.H4(GPMC_A14/QSPI1_D3(I)/TIMER6/SPI)
APL_SCL: J3.1 R193.1 U1.6(SCL)
APL_SDA: J3.3 R192.1 U1.2(SDA)
BT_EN: R224.2 U21.10(BT_EN) U27.AA4(MMC3_DAT6/SPI4_D0/UART10_CTSN/U)
CAM_D0: J14.35(TRD0.9) U27.C8(VIN2A_D0/VOUT2_D23/EMU10/UART9_) U33.24(ROUT0/CSI_D3P)
CAM_D1: J14.37(TRD3.0) U27.B9(VIN2A_D1/VOUT2_D22/EMU11/UART9_) U33.23(ROUT1/CSI_D3N)
CAM_D2: J14.39(TRD3.1) U27.A7(VIN2A_D2/VOUT2_D21/EMU12/UART10) U33.22(ROUT2/CSI_D2P)
CAM_D3: J14.41(TRD3.2) U27.A9(VIN2A_D3/VOUT2_D20/EMU13/UART10) U33.21(ROUT3/CSI_D2N)
CAM_D4: J14.43(TRD3.3) U27.A8(VIN2A_D4/VOUT2_D19/EMU14/UART10) U33.19(ROUT4/CSI_CLKP)
CAM_D5: J14.45(TRD3.4) U27.A11(VIN2A_D5/VOUT2_D18/EMU15/UART10) U33.18(ROUT5/CSI_CLKN)
CAM_D6: J14.47(TRD3.5) U27.F10(VIN2A_D6/VOUT2_D17/EMU16/MII1_R) U33.16(ROUT6/CSI_D1P)
CAM_D7: J14.49(TRD3.6) U27.A10(VIN2A_D7/VOUT2_D16/EMU17/MII1_R) U33.15(ROUT7/CSI_D1N)
CAM_D8: J14.51(TRD3.7) U27.B10(VIN2A_D8/VOUT2_D15/EMU18/MII1_R)
CAM_D9: J14.53(TRD3.8) U27.E10(VIN2A_D9/VOUT2_D14/EMU19/MII1_R)
CAM_DE0: J14.27(TRD0.5) U27.B7(VIN2A_DE0/VIN2A_FLD0/VIN2B_FLD1)
CAM_FLD0: J14.29(TRD0.6) U27.C7(VIN2A_FLD0/VIN2B_CLK1/VOUT2_CLK)
CAM_HSYNC: J14.31(TRD0.7) U27.E8(VIN2A_HSYNC0/VIN2B_HSYNC1/VOUT2) U33.10(HSYNC/GPIO4)
CAM_PCLK: J14.25(TRD0.4) R305.1 U27.D8(VIN2A_CLK0/VOUT2_FLD/EMU5/KBD_R)
CAM_VSYNC: J14.33(TRD0.8) U27.B8(VIN2A_VSYNC0/VIN2B_VSYNC1/VOUT2) U33.9(VSYNC/GPIO5)
CAMERA_LOCK: TP31.1(TP) U27.L6(MDIO_D/UART3_CTSN/MII0_TXER/VIN) U33.48(LOCK)
CAMERA_PDB: C173.1 R334.2 U27.L5(MDIO_MCLK/UART3_RTSN/MII0_COL/V) U33.30(PDB)
CANH_1: J17.4 R151.1 R393.1 U46.7(CANH)
CANH_2: J17.12 R388.1 R393.2 U45.7(CANH)
CANL_1: J17.3 R389.2 R394.1 U46.6(CANL)
CANL_2: J17.11 R152.2 R394.2 U45.6(CANL)
CLK1X_A: C76.1 R57.2
CLK2X_B: R39.2 R221.1 R427.2 U18.1(DEMB)
CLK8X_A: R58.2 RJ2.1 RJ9.1
CLK8X_A_10V5: R60.2 RJ15.3
CLK8X_B: R62.2 RJ2.3 RJ9.3
CLK8X_B_10V5: R61.2 RJ15.1
CLK8X_B_PMIC: R63.2 R303.1 U32.14(GPIO_3 [VRTC])
CON_MMC1_CLK: P10.5(CLK) R406.2 U67.3(IO1)
CON_MMC1_CMD: P10.3(CMD) R405.2 U67.5(IO2)
CON_MMC1_DAT0: P10.7(DAT0) R407.2 U66.5(IO2)
CON_MMC1_DAT1: P10.8(DAT1) R408.2 U66.3(IO1)
CON_MMC1_DAT2: P10.1(DAT2) R403.2 U68.5(IO2)
CON_MMC1_DAT3: P10.2(DAT3) R404.2 U68.3(IO1)
CONN_USB1_DM: FL2.2 J1.2(D-)
CONN_USB1_DP: FL2.3 J1.3(D+)
CONN_USB2_DM: FL1.3 J2.2(D-)
CONN_USB2_DP: FL1.2 J2.3(D+)
CONN_USB_D+: J7.3(D+) U52.14(USBDP)
CONN_USB_D-: J7.2(D-) U52.15(USBDM)
CONN_USB_RXN0: FL5.3 J1.5(STDA_SSRX-) U2.2(D1-) U2.9(NC9)
CONN_USB_RXP0: FL5.2 J1.6(STDA_SSRX+) U2.1(D1+) U2.10(NC10)
CONN_USB_TXN0: FL6.3 J1.8(STDA_SSTX-) U2.5(D2-) U2.6(NC6)
CONN_USB_TXP0: FL6.2 J1.9(STDA_SSTX+) U2.4(D2+) U2.7(NC7)
COUT1M: C85.2 C86.1 C88.2 J9.8 L12.2
COUT1P: C88.1 C90.2 C92.1 J9.7 L13.2
COUT2M: C339.1 C346.2 C355.2 J9.6 L55.2
COUT2P: C355.1 C365.2 C366.1 J9.5 L56.2
COUT3M: C101.1 C102.2 C105.2 J9.4 L14.2
COUT3P: C105.1 C106.2 C111.1 J9.3 L15.2
COUT4M: C389.1 C398.2 C399.2 J9.2 L57.2
COUT4P: C399.1 C404.2 C405.1 J9.1 L58.2
CS_P: C266.1 Q4.1(S) Q5.1(S) R19.1 R38.2
DET_USB1_VBUS: U14.4(O) U27.F2(GPMC_A18/QSPI1_SCLK/GPIO2_8)
DET_USB2_VBUS: U13.4(O) U27.G2(GPMC_A17/QSPI1_D1(I)/GPIO2_7)
EMAC[1]_RXC: U27.E11(VIN2A_D18/VIN2B_D5/RGMII1_RXC/V) U40.27(RX_CLK)
EMAC[1]_RXCTL: U27.F11(VIN2A_D19/VIN2B_D4/RGMII1_RXCTL) U40.15(RX_DV/CRS_DIV/RX_CTRL)
EMAC[1]_RXD0: U27.D13(VIN2A_D23/VIN2B_D0/RGMII1_RXD0/) U40.26(RX_D0)
EMAC[1]_RXD1: U27.C13(VIN2A_D22/VIN2B_D1/RGMII1_RXD1/) U40.25(RX_D1)
EMAC[1]_RXD2: U27.E13(VIN2A_D21/VIN2B_D2/RGMII1_RXD2/) U40.24(RX_D2)
EMAC[1]_RXD3: U27.B13(VIN2A_D20/VIN2B_D3/RGMII1_RXD3/) U40.23(RX_D3)
EMAC[1]_TXC: R101.1 U40.28(TX_CLK)
EMAC[1]_TXCTL: U27.D11(VIN2A_D13/RGMII1_TXCTL/VOUT2_D1) U40.29(TX_EN/TX_CTRL)
EMAC[1]_TXD0: U27.A13(VIN2A_D17/VIN2B_D6/RGMII1_TXD0/) U40.33(TX_D0)
EMAC[1]_TXD1: U27.A12(VIN2A_D16/VIN2B_D7/RGMII1_TXD1/) U40.32(TX_D1)
EMAC[1]_TXD2: U27.B12(VIN2A_D15/RGMII1_TXD2/VOUT2_D8/) U40.31(TX_D2)
EMAC[1]_TXD3: U27.C11(VIN2A_D14/RGMII1_TXD3/VOUT2_D9/) U40.30(TX_D3)
EMU_RSTN: J14.6(NRESET) R263.2 R329.2
ENET_EN: R358.1 U27.H5(GPMC_ADVN_ALE/GPMC_CS6/CLKOUT2/) U40.7(EN)
ENET_INH: R365.1 U27.G6(GPMC_WEN/GPIO2_25) U40.10(INH)
ENET_INTSN: R342.1 R346.1 U27.L4(GPMC_CLK/GPMC_CS7/CLKOUT1/GPMC_)
ENET_WAKE: R360.1 U27.G5(GPMC_OEN_REN/GPIO2_24) U40.8(WAKE)
EXP_GPIO_INTR_43: J19.43 U27.E24(SPI1_CS2/UART4_RXD/MMC3_SDCD/SP)
EXP_GPIO_INTR_77: R165.2 U27.E25(SPI1_CS3/UART4_TXD/MMC3_SDWP/SP)
EXP_GPIO_OUT_57: R184.2 U27.D20(MCASP2_AXR6/MCASP8_ACLKX/MCASP8)
EXP_GPIO_OUT_74: J19.74 U27.C20(MCASP2_AXR7/MCASP8_FSX/MCASP8_F)
FB: R43.1 R49.2 U19.11(FB)
FB_5141: R24.1 R26.2 U18.19(FB)
FPD_DOUT+: C124.2 FL9.1
FPD_DOUT-: C125.2 FL9.4
GNSS_TIME_STAMP: RU2.10(3B2) U21.51(GNSS_TIMESTAMP)
H_CSI2_DX0: P9.5 U27.AC1(CSI2_0_DX0)
H_CSI2_DX1: P9.9 U27.AD1(CSI2_0_DX1)
H_CSI2_DX2: P9.13 U27.AE2(CSI2_0_DX2)
H_CSI2_DY0: P9.7 U27.AB2(CSI2_0_DY0)
H_CSI2_DY1: P9.11 U27.AC2(CSI2_0_DY1)
H_CSI2_DY2: P9.15 U27.AD2(CSI2_0_DY2)
H_DCAN1_RX: R371.1 U27.H23(DCAN1_RX/UART8_TXD/MMC2_SDWP/HD)
H_DCAN1_TX: R372.1 U27.H22(DCAN1_TX/UART8_RXD/MMC2_SDCD/HD)
H_DDR1_A0: R88.2 U23.N3(A0) U27.AC18(DDR1_A0) U29.N3(A0)
H_DDR1_A1: R284.2 U23.P7(A1) U27.AE19(DDR1_A1) U29.P7(A1)
H_DDR1_A2: R85.2 U23.P3(A2) U27.AD19(DDR1_A2) U29.P3(A2)
H_DDR1_A3: R90.2 U23.N2(A3) U27.AB19(DDR1_A3) U29.N2(A3)
H_DDR1_A4: R283.2 U23.P8(A4) U27.AD20(DDR1_A4) U29.P8(A4)
H_DDR1_A5: R287.2 U23.P2(A5) U27.AE20(DDR1_A5) U29.P2(A5)
H_DDR1_A6: R87.2 U23.R8(A6) U27.AA18(DDR1_A6) U29.R8(A6)
H_DDR1_A7: R288.2 U23.R2(A7) U27.AA20(DDR1_A7) U29.R2(A7)
H_DDR1_A8: R86.2 U23.T8(A8) U27.Y21(DDR1_A8) U29.T8(A8)
H_DDR1_A9: R84.2 U23.R3(A9) U27.AC20(DDR1_A9) U29.R3(A9)
H_DDR1_A10: R92.2 U23.L7(A10) U27.AA21(DDR1_A10) U29.L7(A10)
H_DDR1_A11: R285.2 U23.R7(A11) U27.AC21(DDR1_A11) U29.R7(A11)
H_DDR1_A12: R282.2 U23.N7(A12) U27.AC22(DDR1_A12) U29.N7(A12)
H_DDR1_A13: R83.2 U23.T3(A13) U27.AC15(DDR1_A13) U29.T3(A13)
H_DDR1_A14: R286.2 U23.T7(A14) U27.AB15(DDR1_A14) U29.T7(A14)
H_DDR1_A15: R281.2 U23.M7(NC.M7/A15) U27.AC16(DDR1_A15) U29.M7(NC.M7/A15)
H_DDR1_BA0: R280.2 U23.M2(BA0) U27.AE16(DDR1_BA0) U29.M2(BA0)
H_DDR1_BA1: R89.2 U23.N8(BA1) U27.AA16(DDR1_BA1) U29.N8(BA1)
H_DDR1_BA2: R91.2 U23.M3(BA2) U27.AB16(DDR1_BA2) U29.M3(BA2)
H_DDR1_CASN: R95.2 U23.K3(CAS#) U27.AD16(DDR1_CASN) U29.K3(CAS#)
H_DDR1_CKE: R279.2 U23.K9(CKE) U27.AB18(DDR1_CKE) U29.K9(CKE)
H_DDR1_CLK_N: R278.2 U23.K7(CK#) U27.AE21(DDR1_CKN) U29.K7(CK#)
H_DDR1_CLK_P: R94.2 U23.J7(CK) U27.AD21(DDR1_CKP) U29.J7(CK)
H_DDR1_CSN0: R93.2 U23.L2(CS#) U27.AC19(DDR1_CSN0) U29.L2(CS#)
H_DDR1_D0: U23.H7(DQ7) U27.AA23(DDR1_D0)
H_DDR1_D1: U23.F8(DQ3) U27.AC24(DDR1_D1)
H_DDR1_D2: U23.F7(DQ1) U27.AB24(DDR1_D2)
H_DDR1_D3: U23.H8(DQ5) U27.AD24(DDR1_D3)
H_DDR1_D4: U23.E3(DQ0) U27.AB23(DDR1_D4)
H_DDR1_D5: U23.H3(DQ4) U27.AC23(DDR1_D5)
H_DDR1_D6: U23.F2(DQ2) U27.AD23(DDR1_D6)
H_DDR1_D7: U23.G2(DQ6) U27.AE24(DDR1_D7)
H_DDR1_D8: U23.A2(DQ13) U27.AA24(DDR1_D8)
H_DDR1_D9: U23.B8(DQ14) U27.W25(DDR1_D9)
H_DDR1_D10: U23.A7(DQ12) U27.Y23(DDR1_D10)
H_DDR1_D11: U23.C8(DQ10) U27.AD25(DDR1_D11)
H_DDR1_D12: U23.C3(DQ9) U27.AC25(DDR1_D12)
H_DDR1_D13: U23.D7(DQ8) U27.AB25(DDR1_D13)
H_DDR1_D14: U23.A3(DQ15) U27.AA25(DDR1_D14)
H_DDR1_D15: U23.C2(DQ11) U27.W24(DDR1_D15)
H_DDR1_D16: U27.W23(DDR1_D16) U29.F8(DQ3)
H_DDR1_D17: U27.U25(DDR1_D17) U29.H8(DQ5)
H_DDR1_D18: U27.U24(DDR1_D18) U29.F7(DQ1)
H_DDR1_D19: U27.W21(DDR1_D19) U29.F2(DQ2)
H_DDR1_D20: U27.T22(DDR1_D20) U29.E3(DQ0)
H_DDR1_D21: U27.U22(DDR1_D21) U29.G2(DQ6)
H_DDR1_D22: U27.U23(DDR1_D22) U29.H7(DQ7)
H_DDR1_D23: U27.T21(DDR1_D23) U29.H3(DQ4)
H_DDR1_D24: U27.T23(DDR1_D24) U29.C3(DQ9)
H_DDR1_D25: U27.T25(DDR1_D25) U29.A7(DQ12)
H_DDR1_D26: U27.T24(DDR1_D26) U29.B8(DQ14)
H_DDR1_D27: U27.P21(DDR1_D27) U29.A3(DQ15)
H_DDR1_D28: U27.N21(DDR1_D28) U29.C8(DQ10)
H_DDR1_D29: U27.P22(DDR1_D29) U29.C2(DQ11)
H_DDR1_D30: U27.P23(DDR1_D30) U29.A2(DQ13)
H_DDR1_D31: U27.P24(DDR1_D31) U29.D7(DQ8)
H_DDR1_DQM0: U23.E7(LDM) U27.AE23(DDR1_DQM0)
H_DDR1_DQM1: U23.D3(UDM) U27.W22(DDR1_DQM1)
H_DDR1_DQM2: U27.U21(DDR1_DQM2) U29.E7(LDM)
H_DDR1_DQM3: U27.P25(DDR1_DQM3) U29.D3(UDM)
H_DDR1_DQS0_N: U23.G3(LDQS#) U27.AE22(DDR1_DQSN0)
H_DDR1_DQS0_P: U23.F3(LDQS) U27.AD22(DDR1_DQS0)
H_DDR1_DQS1_N: U23.B7(UDQS#) U27.Y25(DDR1_DQSN1)
H_DDR1_DQS1_P: U23.C7(UDQS) U27.Y24(DDR1_DQS1)
H_DDR1_DQS2_N: U27.V25(DDR1_DQSN2) U29.G3(LDQS#)
H_DDR1_DQS2_P: U27.V24(DDR1_DQS2) U29.F3(LDQS)
H_DDR1_DQS3_N: U27.R25(DDR1_DQSN3) U29.B7(UDQS#)
H_DDR1_DQS3_P: U27.R24(DDR1_DQS3) U29.C7(UDQS)
H_DDR1_ODT0: R276.2 U23.K1(ODT) U27.AD18(DDR1_ODT0) U29.K1(ODT)
H_DDR1_RASN: R96.2 U23.J3(RAS#) U27.AD17(DDR1_RASN) U29.J3(RAS#)
H_DDR1_RST: U23.T2(RSTN) U27.AE17(DDR1_RST) U29.T2(RSTN)
H_DDR1_WEN: R277.2 U23.L3(WE#) U27.AE18(DDR1_WEN) U29.L3(WE#)
H_EHRPWM2A: U24.7(2A2) U27.Y5(GPIO6_10/MDIO_MCLK/I2C3_SDA/USB)
H_EHRPWM2B: U24.6(2A1) U27.Y6(GPIO6_11/MDIO_D/I2C3_SCL/US3_UL)
H_EHRPWM3A: RJ5.3 U24.5(1A2) U27.Y3(MMC3_DAT4/SPI4_SCLK/UART10_RXD/)
H_EHRPWM3B: RJ5.1 U24.4(1A1) U27.AA1(MMC3_DAT5/SPI4_D1/UART10_TXD/US)
H_EMU0: J14.19(TRD0.1) R310.2 U27.C21(EMU0/GPIO8_30)
H_EMU1: J14.21(TRD0.2) R311.2 U27.C22(EMU1/GPIO8_31)
H_EMU2: J14.13(TR_CLK0) R292.2
H_EMU3: J14.17(TRD0.0) U27.F14(EMU3)
H_EMU4: J14.23(TRD0.3) U27.F13(EMU4)
H_GPIO5_17: R424.2 U27.P5(RMII_MHZ_50_CLK/VIN2A_D11/XX/GP)
H_HDMI_CLKX: FL4.4 U27.AE9(HDMI1_CLOCKX)
H_HDMI_CLKY: FL4.1 U27.AD10(HDMI1_CLOCKY)
H_HDMI_DX0: FL8.4 U27.AE11(HDMI1_DATA0X)
H_HDMI_DX1: FL7.4 U27.AE12(HDMI1_DATA1X)
H_HDMI_DX2: FL3.4 U27.AE14(HDMI1_DATA2X)
H_HDMI_DY0: FL8.1 U27.AD12(HDMI1_DATA0Y)
H_HDMI_DY1: FL7.1 U27.AD13(HDMI1_DATA1Y)
H_HDMI_DY2: FL3.1 U27.AD15(HDMI1_DATA2Y)
H_I2C1_SCL: R193.2 R234.1 U22.6(SCL) U26.6(SCL2) U27.G22(I2C1_SCL) U28.20(SCL) U32.35(I2C1_SCL_SCK [VIO_IN])
H_I2C1_SDA: R192.2 R233.1 U22.5(SDA) U26.5(SDA2) U27.G23(I2C1_SDA) U28.21(SDA) U32.36(I2C1_SDA_SDI [VIO_IN])
H_I2C5_SCL: J19.79 U27.B14(MCASP1_AXR1/UART6_TXD/VIN1A_HSY)
H_I2C5_SDA: J19.80 U27.D14(MCASP1_AXR0/UART6_RXD/VIN1A_VSY)
H_JTAG_RTCK: J14.7(RTCK) R70.2
H_JTAG_TCK: J14.3(TCK) R307.2 U27.K21(TCLK)
H_JTAG_TDI: J14.5(TDI) U27.L23(TDI/GPIO8_27)
H_JTAG_TDO: J14.4(TDO) R264.2
H_JTAG_TMS: J14.2(TMS) R328.2 U27.L21(TMS)
H_JTAG_TRSTN: RJ26.2 U27.L22(TRSTN)
H_MCASP1_ACLKR_I2C4_SDA: R173.2 R179.1 U27.D16(MCASP1_ACLKR/MCASP7_AXR2/I2C4_S)
H_MCASP1_ACLKX: J19.13 R103.1
H_MCASP1_AXR2: J19.14 U27.C14(MCASP1_AXR2/MCASP6_AXR2/UART6_C)
H_MCASP1_AXR3: J19.15 U27.B15(MCASP1_AXR3/MCASP6_AXR3/UART6_R)
H_MCASP1_AXR4: J19.16 U27.A15(MCASP1_AXR4/MCASP4_AXR2/GPIO5_6)
H_MCASP1_AXR5: J19.18 U27.A14(MCASP1_AXR5/MCASP4_AXR3/GPIO5_7)
H_MCASP1_AXR6: J19.19 U27.A17(MCASP1_AXR6/MCASP5_AXR2/GPIO5_8)
H_MCASP1_AXR7: J19.20 U27.A16(MCASP1_AXR7/MCASP5_AXR3/TIMER4/)
H_MCASP1_AXR8: J19.21 U27.A18(MCASP1_AXR8/MCASP6_AXR0/SPI3_SC)
H_MCASP1_AXR12: RJ30.2 U27.A19(MCASP1_AXR12/MCASP7_AXR0/SPI3_C)
H_MCASP1_FSR_I2C4_SCL: R174.2 R180.1 U27.D17(MCASP1_FSR/MCASP7_AXR3/I2C4_SCL)
H_MCASP1_FSX: J19.12 U27.C17(MCASP1_FSX/VIN1A_DE0/I2C3_SCL/P)
H_MCASP2_ACLKX: R267.1 TP68.1(TP) U36.50(ZIFCLK) U55.6(2Y)
H_MCASP2_AXR0: TP73.1(TP) U27.A20(MCASP2_AXR0) U55.3(1Y)
H_MCASP2_AXR1: TP72.1(TP) U27.B19(MCASP2_AXR1) U55.8(3Y)
H_MCASP2_AXR4: U27.B20(MCASP2_AXR4/MCASP8_AXR0/GPIO1_4) U56.8(3Y)
H_MCASP2_AXR5: U27.C19(MCASP2_AXR5/MCASP8_AXR1/GPIO6_7) U56.11(4Y)
H_MCASP2_FSX: TP69.1(TP) U27.D19(MCASP2_FSX/VIN1A_D6/PR2_MII0_RX) U36.48(ZIFFS) U55.11(4Y)
H_MCASP3_ACLKX: R98.1 TP70.1(TP) U36.60(DCLK0)
H_MCASP3_AXR0: U27.B22(MCASP3_AXR0/MCASP2_AXR14/UART7_) U36.67(DIN3)
H_MCASP3_AXR1: U27.B23(MCASP3_AXR1/MCASP2_AXR15/UART7_) U36.64(DIN4)
H_MCASP3_AXR2: U27.A21(MCASP2_AXR2/MCASP3_AXR2/VIN1A_D) U56.3(1Y)
H_MCASP3_AXR3: U27.B21(MCASP2_AXR3/MCASP3_AXR3/VIN1A_D) U56.6(2Y)
H_MCASP3_FSX: TP71.1(TP) U27.A23(MCASP3_FSX/MCASP3_FSR/MCASP2_AX) U36.59(DFSO)
H_MCASP4_ACLKX: R97.1 R257.2 RJ29.3
H_MCASP4_AXR0: R253.2 U27.A24(MCASP4_AXR0/SPI3_D0/UART8_CTSN/)
H_MCASP4_AXR1: R252.2 U27.D23(MCASP4_AXR1/SPI3_CS0/UART8_RTSN)
H_MCASP4_FSX: R256.2 U27.B25(MCASP4_FSX/MCASP4_FSR/SPI3_D1/U)
H_MCASP5_ACLKX: R429.1 U21.7(BT_PCM_CLK)
H_MCASP5_AXR0: U21.8(BT_PCM_OUT) U27.AA5(MCASP5_AXR0/SPI4_D0/UART9_CTSN/)
H_MCASP5_AXR1: U21.5(BT_PCM_IN) U27.AC4(MCASP5_AXR1/SPI4_CS0/UART9_RTSN)
H_MCASP5_FSX: U21.6(BT_PCM_FSYNC) U27.U6(MCASP5_FSX/MCASP5_FSR/SPI4_D1/U)
H_MCASP6_ACLKX_ACLKR: J19.87 R100.1
H_MCASP6_AXR1: J19.88 U27.B17(MCASP1_AXR9/MCASP6_AXR1/SPI3_D1)
H_MCASP6_FSX_FSR: J19.89 U27.B18(MCASP1_AXR11/MCASP6_FSX/MCASP6_)
H_MCASP7_ACLKX_ACLKR: J19.92 R102.1
H_MCASP7_AXR0: J19.31 RJ30.1
H_MCASP7_AXR1: J19.91 U27.E17(MCASP1_AXR13/MCASP7_AXR1/VIN1A_)
H_MCASP7_FSX_FSR: J19.90 U27.F16(MCASP1_AXR15/MCASP7_FSX/MCASP7_)
H_MCU_DCAN1_STB: R426.1 U27.P2(RGMII0_RXCTL/RMII1_TXD1/MII0_TX)
H_MCU_GPIO_1: R327.1 U27.N1(RGMII0_RXD3/RMII1_TXD0/MII0_TXD)
H_MCU_GPIO_2: R331.1 U27.P1(RGMII0_RXD2/RMII0_TXEN/MII0_TXE)
H_MCU_GPIO_3: R335.1 U27.N3(RGMII0_RXD1/RMII0_TXD1/MII0_TXD)
H_MCU_GPIO_4: R341.1 U27.N4(RGMII0_RXD0/RMII0_TXD0/MII0_TXD)
H_MMC1_CLK: R66.1 R226.2 RU1.12(4A)
H_MMC1_CMD: R227.2 RU1.9(3A) U27.V4(MMC1_CMD/GPIO6_22)
H_MMC1_D0: R228.2 RU2.4(1A) U27.V3(MMC1_D0/GPIO6_23)
H_MMC1_D1: R230.2 RU2.7(2A) U27.V2(MMC1_D1/GPIO6_24)
H_MMC1_D2: R231.2 RU1.4(1A) U27.W1(MMC1_D2/GPIO6_25)
H_MMC1_D3: R229.2 RU1.7(2A) U27.V1(MMC1_D3/GPIO6_26)
H_MMC1_SDCD: R410.2 R411.1 U27.U5(MMC1_SDCD/UART6_RXD/I2C4_SDA/GP)
H_MMC1_SDWP: RU2.9(3A) U27.V5(MMC1_SDWP/UART6_TXD/I2C4_SCL/GP)
H_MMC1_SELN: R425.1 RU1.1(S) RU2.1(S) U27.N2(RGMII0_RXC/RMII1_TXEN/MII0_TXCL)
H_NMIN_DSP: R71.2 U27.L24(NMIN_DSP)
H_PMIC_INTN: R236.1 U27.AB10(WAKEUP3/SYS_NIRQ1/GPIO1_3/DCAN2) U32.26(INT [VIO_IN])
H_PORZ: TP40.1(TP) U27.F19(PORZ) U32.25(RESET_OUT [VIO_IN]) U40.3(RESET_N)
H_RSTOUTN: J21.29 R104.2 TP36.1(TP) U27.E20(RSTOUTN) U32.13(GPIO_1 [VRTC]) U54.1(OE)
H_SPI1_CS0: U27.B24(SPI1_CS0/GPIO7_10) U36.43(SSB)
H_SPI1_CS1: U27.C25(SPI1_CS1/SPI2_CS1/GPIO7_11) U34.23(SSB)
H_SPI1_D0: U27.D25(SPI1_D0/GPIO7_9) U34.21(MOSI) U36.41(MOSI)
H_SPI1_D1: U27.D24(SPI1_D1/GPIO7_8) U34.20(MISO) U36.40(MISO)
H_SPI1_SCLK: R81.2 U34.22(SCLK) U36.42(SCLK)
H_SPI2_CS0: J19.85 U27.F24(SPI2_CS0/UART3_RTSN/UART5_TXD/G)
H_SPI2_D0: J19.83 U27.G24(SPI2_D0/UART3_CTSN/UART5_RXD/GP)
H_SPI2_D1: J19.84 U27.F25(SPI2_D1/UART3_TXD/GPIO7_15)
H_SPI2_SCLK: J19.82 R77.2
H_SPI4_CS0: J19.62 U27.R1(RGMII0_TXD0/RMII0_RXD0/MII0_RXD)
H_SPI4_CS1: J19.64 U27.N6(UART3_TXD/RMII1_RXER/MII0_RXCLK)
H_SPI4_CS2: J19.65 U27.T4(RGMII0_TXC/UART3_CTSN/RMII1_RXD)
H_SPI4_CS3: J19.66 U27.T5(RGMII0_TXCTL/UART3_RTSN/RMII1_R)
H_SPI4_D0: J19.60 U27.R2(RGMII0_TXD1/RMII0_RXD1/MII0_RXD)
H_SPI4_D1: J19.61 U27.P3(RGMII0_TXD2/RMII0_RXER/MII0_RXE)
H_SPI4_SCLK: J19.59 R183.1
H_UART1_RXD: R357.1 U27.L25(UART1_RXD/MMC4_SDCD/GPIO7_22)
H_UART1_TXD: R356.1 U27.M25(UART1_TXD/MMC4_SDWP/GPIO7_23)
H_UART3_RXD_BOOT: R232.1 U27.N22(UART2_CTSN/UART3_IRRX/MMC4_DAT2)
H_UART3_TXD_BOOT: R56.2 U27.N24(UART2_RTSN/UART3_TXD/UART3_IRTX) U52.2(RXD)
H_UART5_CTSN: U21.62(BT_UART_RTS) U27.AA3(MMC3_DAT2/SPI3_CS0/UART5_CTSN/U)
H_UART5_RTSN: U21.63(BT_UART_CTS) U27.W2(MMC3_DAT3/SPI3_CS1/UART5_RTSN/U)
H_UART5_RXD: U21.60(BT_UART_TX) U27.Y4(MMC3_DAT0/SPI3_D1/UART5_RXD/USB)
H_UART5_TXD: U21.61(BT_UART_RX) U27.AA2(MMC3_DAT1/SPI3_D0/UART5_TXD/USB)
H_UART9_RXD: R65.2 U27.L20(UART1_CTSN/UART9_RXD/MMC4_CLK/G)
H_UART9_TXD: R67.2 U27.M24(UART1_RTSN/UART9_TXD/MMC4_CMD/G)
H_USB1_DN: U11.4(DM_OUT) U27.AB7(USB1_DN)
H_USB1_DP: U11.5(DP_OUT) U27.AC6(USB1_DP)
H_USB1_DRVVBUS: R8.1 R9.1 R11.1 U27.AD3(USB1_DRVVBUS/TIMER16/GPIO6_12)
H_USB2_DN: U12.12(D-) U27.AC5(USB2_DN)
H_USB2_DP: U12.11(D+) U27.AB6(USB2_DP)
H_USB2_DRVVBUS: Q2.2(G2) R13.1 U27.AA6(USB2_DRVVBUS/TIMER15/GPIO6_13)
H_USB3_RXN: FL5.4 U27.AE5(USB_RXN0/PCIE_RXN1)
H_USB3_RXP: FL5.1 U27.AD6(USB_RXP0/PCIE_RXP1)
H_USB3_TXN: C14.1 U27.AE3(USB_TXN0/PCIE_TXN1)
H_USB3_TXP: C13.1 U27.AD4(USB_TXP0/PCIE_TXP1)
H_XREF_CLK0: R72.2 R164.2
H_XREF_CLK1: R74.2 R168.2
H_XREF_CLK3: R75.2 RJ29.1
HDMI_CEC_A: U17.24(CEC_A) U27.N25(UART2_TXD/UART3_RTSN/UART3_SD/M)
HDMI_CEC_B: P1.13(CE REMOTE) R27.1 U17.6(CEC_B)
HDMI_DSCL: R212.1 R265.1 U17.1(SCL_A)
HDMI_DSDA: R215.1 R266.1 U17.2(SDA_A)
HDMI_HPD: R25.1 U27.N23(UART2_RXD/UART3_CTSN/UART3_RCTX)
HDMI_HPD_B: P1.19(HP DET) R31.2 R32.1 U17.9(HPD_B)
HDMI_SCL_B: P1.15(DDC CLK) R28.1 U17.7(SCL_B)
HDMI_SDA_B: P1.16(DDC DATA) R30.1 U17.8(SDA_B)
HDMI_TX0+: FL8.2 P1.7(D0+) U9.1(IO)
HDMI_TX0-: FL8.3 P1.9(D0-) U10.1(IO)
HDMI_TX1+: FL7.2 P1.4(D1+) U7.1(IO)
HDMI_TX1-: FL7.3 P1.6(D1-) U8.1(IO)
HDMI_TX2+: FL3.2 P1.1(D2+) U3.1(IO)
HDMI_TX2-: FL3.3 P1.3(D2-) U4.1(IO)
HDMI_TXC+: FL4.2 P1.10(CK+) U5.1(IO)
HDMI_TXC-: FL4.3 P1.12(CK-) U6.1(IO)
HDRV1_N: C50.2 L2.1 Q4.5(D) Q6.1(S) U19.28(SW1)
HDRV1_P: R14.2 U19.27(HDRV1)
HDRV2_N: C47.1 D4.2(ANODE) D7.1(CATHODE) L2.2 Q5.5(D) Q7.1(S) U19.18(SW2)
HDRV2_P: R15.1 U19.19(HDRV2)
HUB0_AIN2_N: C531.1 R397.2 U36.24(AIN2N)
HUB0_AIN2_P: C535.1 R398.1 U36.23(AIN2P)
HUB0_AIN3_N: C520.1 R387.2 U36.26(AIN3N)
HUB0_AIN3_P: C530.1 R390.1 U36.25(AIN3P)
HUB0_AIN4_N: C502.1 R359.2 U36.28(AIN4N)
HUB0_AIN4_P: C513.1 R361.1 U36.27(AIN4P)
HUB0_AIN5_N: C473.1 R318.2 U36.30(AIN5N)
HUB0_AIN5_P: C490.1 R321.1 U36.29(AIN5P)
HUB0_AIN6_N: C438.1 R301.2 U36.32(AIN6N)
HUB0_AIN6_P: C449.1 R302.1 U36.31(AIN6P)
HUB0_CLKO: FB1.1 R325.2
HUB_AOUT0: C94.2 U36.82(AOUT0)
HUB_AOUT1: C99.2 U36.83(AOUT1)
HUB_AOUT2: C103.2 U36.84(AOUT2)
HUB_AOUT3: C109.2 U36.1(AOUT3)
I2C4_SCL: R174.1 R181.1 U30.8(SCL) U33.2(I2C_SCL)
